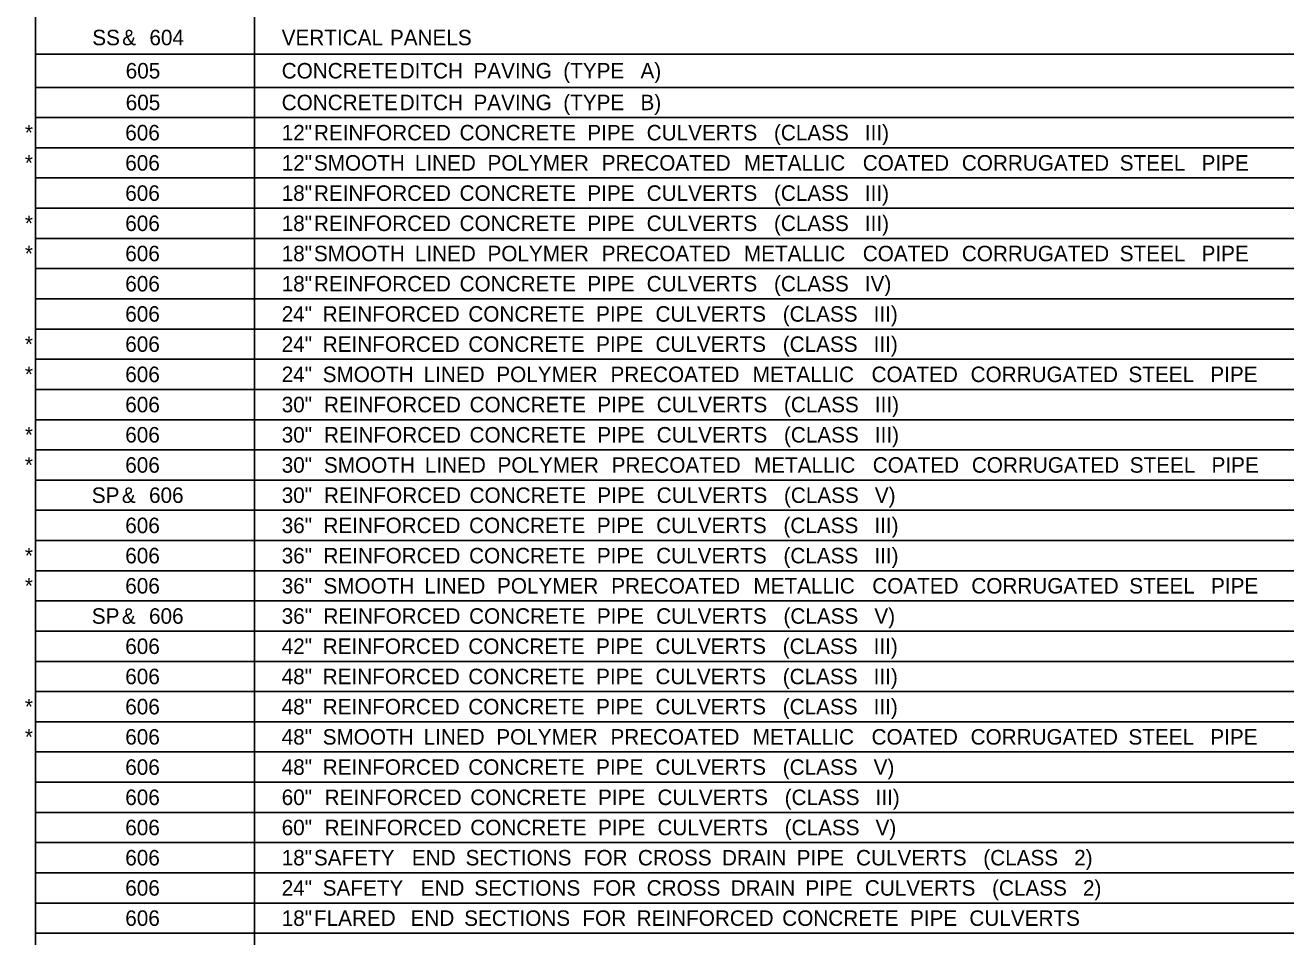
# Model space of a CAD drawing. Extents: x 1226603 to 1228117, y 151305 to 152343.
# Drawn here: x 1226603 to 1226948.8, y 151587 to 151837.1 of the extents above; entities that cross this region are included whole.
import ezdxf

# ---------------------------------------------------------------- set-up
doc = ezdxf.new("R2010")
doc.units = 0
doc.layers.add('R_Dimension', color=7, linetype='Continuous')

msp = doc.modelspace()

# ---------------------------------------------------------------- linework, layer by layer
at = {"layer": 'R_Dimension'}
for p, q in [((1226605.78, 151338.98), (1226605.78, 152334.72)), ((1226665.86, 151338.98), (1226665.86, 152334.72)), ((1226605.78, 151829.18), (1227235.63, 151829.18)), ((1226605.78, 151820.06), (1227235.63, 151820.06)), ((1226605.78, 151811.78), (1227235.63, 151811.78)), ((1226605.78, 151803.49), (1227235.63, 151803.49)), ((1226605.78, 151795.2), (1227235.63, 151795.2)), ((1226605.78, 151786.91), (1227235.63, 151786.91)), ((1226605.78, 151778.63), (1227235.63, 151778.63)), ((1226605.78, 151770.34), (1227235.63, 151770.34)), ((1226605.78, 151762.05), (1227235.63, 151762.05)), ((1226605.78, 151753.76), (1227235.63, 151753.76)), ((1226605.78, 151745.48), (1227235.63, 151745.48)), ((1226605.78, 151737.19), (1227235.63, 151737.19)), ((1226605.78, 151728.9), (1227235.63, 151728.9)), ((1226605.78, 151720.61), (1227235.63, 151720.61)), ((1226605.78, 151712.33), (1227235.63, 151712.33)), ((1226605.78, 151704.04), (1227235.63, 151704.04)), ((1226605.78, 151695.75), (1227235.63, 151695.75)), ((1226605.78, 151687.46), (1227235.63, 151687.46)), ((1226605.78, 151679.18), (1227235.63, 151679.18)), ((1226605.78, 151670.89), (1227235.63, 151670.89)), ((1226605.78, 151662.6), (1227235.63, 151662.6)), ((1226605.78, 151654.31), (1227235.63, 151654.31)), ((1226605.78, 151646.03), (1227235.63, 151646.03)), ((1226605.78, 151637.74), (1227235.63, 151637.74)), ((1226605.78, 151629.45), (1227235.63, 151629.45)), ((1226605.78, 151621.16), (1227235.63, 151621.16)), ((1226605.78, 151612.88), (1227235.63, 151612.88)), ((1226605.78, 151604.59), (1227235.63, 151604.59)), ((1226605.78, 151596.3), (1227235.63, 151596.3)), ((1226605.78, 151588.01), (1227235.63, 151588.01))]:
    msp.add_line(p, q, dxfattribs=at)

# ---------------------------------------------------------------- texts
for s, p in [('SS', (1226621.36, 151831.61)), (' &', (1226627.99, 151831.61)), (' 604', (1226635.45, 151831.61)), ('VERTICAL', (1226673.32, 151831.61)), (' PANELS', (1226701.43, 151831.61)), ('605', (1226630.53, 151822.5)), ('CONCRETE', (1226673.32, 151822.5)), (' DITCH', (1226704.11, 151822.5)), (' PAVING', (1226724.35, 151822.5)), (' (TYPE', (1226748.98, 151822.5)), (' A)', (1226770.17, 151822.5)), ('605', (1226630.53, 151813.8)), ('CONCRETE', (1226673.32, 151813.8)), (' DITCH', (1226704.11, 151813.8)), (' PAVING', (1226724.35, 151813.8)), (' (TYPE', (1226748.98, 151813.8)), (' B)', (1226770.17, 151813.8)), ('*', (1226602.87, 151805.51)), ('606', (1226630.41, 151805.51)), ('12"', (1226673.32, 151805.51)), (' REINFORCED', (1226680.58, 151805.51)), (' CONCRETE', (1226720.54, 151805.51)), (' PIPE', (1226755.58, 151805.51)), (' CULVERTS', (1226771.87, 151805.51)), (' (CLASS', (1226806.78, 151805.51)), (' III)', (1226831.71, 151805.51)), ('*', (1226602.87, 151797.22)), ('606', (1226630.41, 151797.22)), ('12"', (1226673.32, 151797.22)), (' SMOOTH', (1226680.58, 151797.22)), (' LINED', (1226708.26, 151797.22)), (' POLYMER', (1226728.2, 151797.22)), (' PRECOATED', (1226759.52, 151797.22)), (' METALLIC', (1226798.54, 151797.22)), (' COATED', (1226831.14, 151797.22)), (' CORRUGATED', (1226858.31, 151797.22)), (' STEEL', (1226901.62, 151797.22)), (' PIPE', (1226924.07, 151797.22)), ('606', (1226630.41, 151788.93)), ('18"', (1226673.32, 151788.93)), (' REINFORCED', (1226680.58, 151788.93)), (' CONCRETE', (1226720.54, 151788.93)), (' PIPE', (1226755.58, 151788.93)), (' CULVERTS', (1226771.87, 151788.93)), (' (CLASS', (1226806.78, 151788.93)), (' III)', (1226831.71, 151788.93)), ('*', (1226602.87, 151780.65)), ('606', (1226630.41, 151780.65)), ('18"', (1226673.32, 151780.65)), (' REINFORCED', (1226680.58, 151780.65)), (' CONCRETE', (1226720.54, 151780.65)), (' PIPE', (1226755.58, 151780.65)), (' CULVERTS', (1226771.87, 151780.65)), (' (CLASS', (1226806.78, 151780.65)), (' III)', (1226831.71, 151780.65)), ('*', (1226602.87, 151772.36)), ('606', (1226630.41, 151772.36)), ('18"', (1226673.32, 151772.36)), (' SMOOTH', (1226680.58, 151772.36)), (' LINED', (1226708.26, 151772.36)), (' POLYMER', (1226728.2, 151772.36)), (' PRECOATED', (1226759.52, 151772.36)), (' METALLIC', (1226798.54, 151772.36)), (' COATED', (1226831.14, 151772.36)), (' CORRUGATED', (1226858.31, 151772.36)), (' STEEL', (1226901.62, 151772.36)), (' PIPE', (1226924.07, 151772.36)), ('606', (1226630.41, 151764.07)), ('18"', (1226673.32, 151764.07)), (' REINFORCED', (1226680.58, 151764.07)), (' CONCRETE', (1226720.54, 151764.07)), (' PIPE', (1226755.58, 151764.07)), (' CULVERTS', (1226771.87, 151764.07)), (' (CLASS', (1226806.78, 151764.07)), (' IV)', (1226831.71, 151764.07)), ('606', (1226630.41, 151755.78)), ('24"', (1226673.32, 151755.78)), (' REINFORCED', (1226682.99, 151755.78)), (' CONCRETE', (1226722.95, 151755.78)), (' PIPE', (1226757.99, 151755.78)), (' CULVERTS', (1226774.28, 151755.78)), (' (CLASS', (1226809.19, 151755.78)), (' III)', (1226834.12, 151755.78)), ('*', (1226602.87, 151747.5)), ('606', (1226630.41, 151747.5)), ('24"', (1226673.32, 151747.5)), (' REINFORCED', (1226682.99, 151747.5)), (' CONCRETE', (1226722.95, 151747.5)), (' PIPE', (1226757.99, 151747.5)), (' CULVERTS', (1226774.28, 151747.5)), (' (CLASS', (1226809.19, 151747.5)), (' III)', (1226834.12, 151747.5)), ('*', (1226602.87, 151739.21)), ('606', (1226630.41, 151739.21)), ('24"', (1226673.32, 151739.21)), (' SMOOTH', (1226682.99, 151739.21)), (' LINED', (1226710.67, 151739.21)), (' POLYMER', (1226730.61, 151739.21)), (' PRECOATED', (1226761.93, 151739.21)), (' METALLIC', (1226800.95, 151739.21)), (' COATED', (1226833.55, 151739.21)), (' CORRUGATED', (1226860.72, 151739.21)), (' STEEL', (1226904.02, 151739.21)), (' PIPE', (1226926.48, 151739.21)), ('606', (1226630.41, 151730.92)), ('30"', (1226673.32, 151730.92)), (' REINFORCED', (1226683.33, 151730.92)), (' CONCRETE', (1226723.28, 151730.92)), (' PIPE', (1226758.32, 151730.92)), (' CULVERTS', (1226774.62, 151730.92)), (' (CLASS', (1226809.52, 151730.92)), (' III)', (1226834.45, 151730.92)), ('*', (1226602.87, 151722.63)), ('606', (1226630.41, 151722.63)), ('30"', (1226673.32, 151722.63)), (' REINFORCED', (1226683.33, 151722.63)), (' CONCRETE', (1226723.28, 151722.63)), (' PIPE', (1226758.32, 151722.63)), (' CULVERTS', (1226774.62, 151722.63)), (' (CLASS', (1226809.52, 151722.63)), (' III)', (1226834.45, 151722.63)), ('*', (1226602.87, 151714.35)), ('606', (1226630.41, 151714.35)), ('30"', (1226673.32, 151714.35)), (' SMOOTH', (1226683.33, 151714.35)), (' LINED', (1226711, 151714.35)), (' POLYMER', (1226730.95, 151714.35)), (' PRECOATED', (1226762.27, 151714.35)), (' METALLIC', (1226801.29, 151714.35)), (' COATED', (1226833.88, 151714.35)), (' CORRUGATED', (1226861.06, 151714.35)), (' STEEL', (1226904.36, 151714.35)), (' PIPE', (1226926.81, 151714.35)), ('SP', (1226621.23, 151706.06)), (' &', (1226627.89, 151706.06)), (' 606', (1226635.35, 151706.06)), ('30"', (1226673.32, 151706.06)), (' REINFORCED', (1226683.33, 151706.06)), (' CONCRETE', (1226723.28, 151706.06)), (' PIPE', (1226758.32, 151706.06)), (' CULVERTS', (1226774.62, 151706.06)), (' (CLASS', (1226809.52, 151706.06)), (' V)', (1226834.45, 151706.06)), ('606', (1226630.41, 151697.77)), ('36"', (1226673.32, 151697.77)), (' REINFORCED', (1226683.19, 151697.77)), (' CONCRETE', (1226723.15, 151697.77)), (' PIPE', (1226758.19, 151697.77)), (' CULVERTS', (1226774.48, 151697.77)), (' (CLASS', (1226809.39, 151697.77)), (' III)', (1226834.32, 151697.77)), ('*', (1226602.87, 151689.48)), ('606', (1226630.41, 151689.48)), ('36"', (1226673.32, 151689.48)), (' REINFORCED', (1226683.19, 151689.48)), (' CONCRETE', (1226723.15, 151689.48)), (' PIPE', (1226758.19, 151689.48)), (' CULVERTS', (1226774.48, 151689.48)), (' (CLASS', (1226809.39, 151689.48)), (' III)', (1226834.32, 151689.48)), ('*', (1226602.87, 151681.2)), ('606', (1226630.41, 151681.2)), ('36"', (1226673.32, 151681.2)), (' SMOOTH', (1226683.19, 151681.2)), (' LINED', (1226710.87, 151681.2)), (' POLYMER', (1226730.81, 151681.2)), (' PRECOATED', (1226762.13, 151681.2)), (' METALLIC', (1226801.15, 151681.2)), (' COATED', (1226833.75, 151681.2)), (' CORRUGATED', (1226860.92, 151681.2)), (' STEEL', (1226904.23, 151681.2)), (' PIPE', (1226926.68, 151681.2)), ('SP', (1226621.23, 151672.91)), (' &', (1226627.89, 151672.91)), (' 606', (1226635.35, 151672.91)), ('36"', (1226673.32, 151672.91)), (' REINFORCED', (1226683.19, 151672.91)), (' CONCRETE', (1226723.15, 151672.91)), (' PIPE', (1226758.19, 151672.91)), (' CULVERTS', (1226774.48, 151672.91)), (' (CLASS', (1226809.39, 151672.91)), (' V)', (1226834.32, 151672.91)), ('606', (1226630.41, 151664.62)), ('42"', (1226673.32, 151664.62)), (' REINFORCED', (1226682.99, 151664.62)), (' CONCRETE', (1226722.95, 151664.62)), (' PIPE', (1226757.99, 151664.62)), (' CULVERTS', (1226774.28, 151664.62)), (' (CLASS', (1226809.19, 151664.62)), (' III)', (1226834.12, 151664.62)), ('606', (1226630.41, 151656.33)), ('48"', (1226673.32, 151656.33)), (' REINFORCED', (1226682.99, 151656.33)), (' CONCRETE', (1226722.95, 151656.33)), (' PIPE', (1226757.99, 151656.33)), (' CULVERTS', (1226774.28, 151656.33)), (' (CLASS', (1226809.19, 151656.33)), (' III)', (1226834.12, 151656.33)), ('*', (1226602.87, 151648.05)), ('606', (1226630.41, 151648.05)), ('48"', (1226673.32, 151648.05)), (' REINFORCED', (1226682.99, 151648.05)), (' CONCRETE', (1226722.95, 151648.05)), (' PIPE', (1226757.99, 151648.05)), (' CULVERTS', (1226774.28, 151648.05)), (' (CLASS', (1226809.19, 151648.05)), (' III)', (1226834.12, 151648.05)), ('*', (1226602.87, 151639.76)), ('606', (1226630.41, 151639.76)), ('48"', (1226673.32, 151639.76)), (' SMOOTH', (1226682.99, 151639.76)), (' LINED', (1226710.67, 151639.76)), (' POLYMER', (1226730.61, 151639.76)), (' PRECOATED', (1226761.93, 151639.76)), (' METALLIC', (1226800.95, 151639.76)), (' COATED', (1226833.55, 151639.76)), (' CORRUGATED', (1226860.72, 151639.76)), (' STEEL', (1226904.02, 151639.76)), (' PIPE', (1226926.48, 151639.76)), ('606', (1226630.41, 151631.47)), ('48"', (1226673.32, 151631.47)), (' REINFORCED', (1226682.99, 151631.47)), (' CONCRETE', (1226722.95, 151631.47)), (' PIPE', (1226757.99, 151631.47)), (' CULVERTS', (1226774.28, 151631.47)), (' (CLASS', (1226809.19, 151631.47)), (' V)', (1226834.12, 151631.47)), ('606', (1226630.41, 151623.18)), ('60"', (1226673.32, 151623.18)), (' REINFORCED', (1226683.53, 151623.18)), (' CONCRETE', (1226723.48, 151623.18)), (' PIPE', (1226758.52, 151623.18)), (' CULVERTS', (1226774.82, 151623.18)), (' (CLASS', (1226809.72, 151623.18)), (' III)', (1226834.65, 151623.18)), ('606', (1226630.41, 151614.9)), ('60"', (1226673.32, 151614.9)), (' REINFORCED', (1226683.53, 151614.9)), (' CONCRETE', (1226723.48, 151614.9)), (' PIPE', (1226758.52, 151614.9)), (' CULVERTS', (1226774.82, 151614.9)), (' (CLASS', (1226809.72, 151614.9)), (' V)', (1226834.65, 151614.9)), ('606', (1226630.41, 151606.61)), ('18"', (1226673.32, 151606.61)), (' SAFETY', (1226680.58, 151606.61)), (' END', (1226707.45, 151606.61)), (' SECTIONS', (1226722.18, 151606.61)), (' FOR', (1226754.61, 151606.61)), (' CROSS', (1226769.46, 151606.61)), (' DRAIN', (1226792.52, 151606.61)), (' PIPE', (1226813, 151606.61)), (' CULVERTS', (1226829.3, 151606.61)), (' (CLASS', (1226864.2, 151606.61)), (' 2)', (1226889.13, 151606.61)), (' (CLASS', (1226866.61, 151598.32)), (' 2)', (1226891.54, 151598.32)), ('606', (1226630.41, 151598.32)), ('24"', (1226673.32, 151598.32)), (' SAFETY', (1226682.99, 151598.32)), (' END', (1226709.86, 151598.32)), (' SECTIONS', (1226724.59, 151598.32)), (' FOR', (1226757.01, 151598.32)), (' CROSS', (1226771.87, 151598.32)), (' DRAIN', (1226794.93, 151598.32)), (' PIPE', (1226815.41, 151598.32)), (' CULVERTS', (1226831.71, 151598.32)), ('606', (1226630.41, 151590.03)), ('18"', (1226673.32, 151590.03)), (' FLARED', (1226680.58, 151590.03)), (' END', (1226707.09, 151590.03)), (' SECTIONS', (1226721.81, 151590.03)), (' FOR', (1226754.24, 151590.03)), (' REINFORCED', (1226769.1, 151590.03)), (' CONCRETE', (1226809.05, 151590.03)), (' PIPE', (1226844.09, 151590.03)), (' CULVERTS', (1226860.39, 151590.03))]:
    msp.add_text(s, height=4.25, dxfattribs=at).set_placement(p)

doc.saveas('drawing.dxf')
